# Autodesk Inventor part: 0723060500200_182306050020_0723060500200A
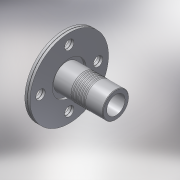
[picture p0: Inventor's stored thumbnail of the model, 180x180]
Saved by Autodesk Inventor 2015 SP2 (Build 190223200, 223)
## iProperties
Created: 2017-02
Part Number: 0723060500200_182306050020_0723060500200A
Material: PVC-Piping
Description: PLASSON FLANGE ADAPTOR WITH METAL FLANGE 50-2"
Document SubType Name: Modeling
Designer: KIM
Mass: 92.6774 g
Surface Area: 199.44 cm^2
Volume: 66.1981 cm^3
Density: 1.4 g/cm^3
Appearance: Smooth - White
Author: KIM
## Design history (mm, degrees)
derived "072306.ipt"
feature "Solid1::072306.ipt"
tag "TaggingFeature1"
body "Solid1"
other parameters: "d73" = 9.9, "d74" = 90 deg, "d75" = 0.3, "d76" = 165, "d77" = 18, "d78" = 62.5, "d80" = 0, "d82" = 360 deg, "d96" = 0.3, "d99" = 360 deg, "d102" = 35, "d103" = 99, "d104" = 1, "d107" = 65, "d108" = 2.475, "d109" = 49, "d110" = 39.6, "d111" = 5, "d115" = 5, "E_" = 82, "H_" = 99, "D_" = 165, "Dp_" = 125, "S_" = 18
